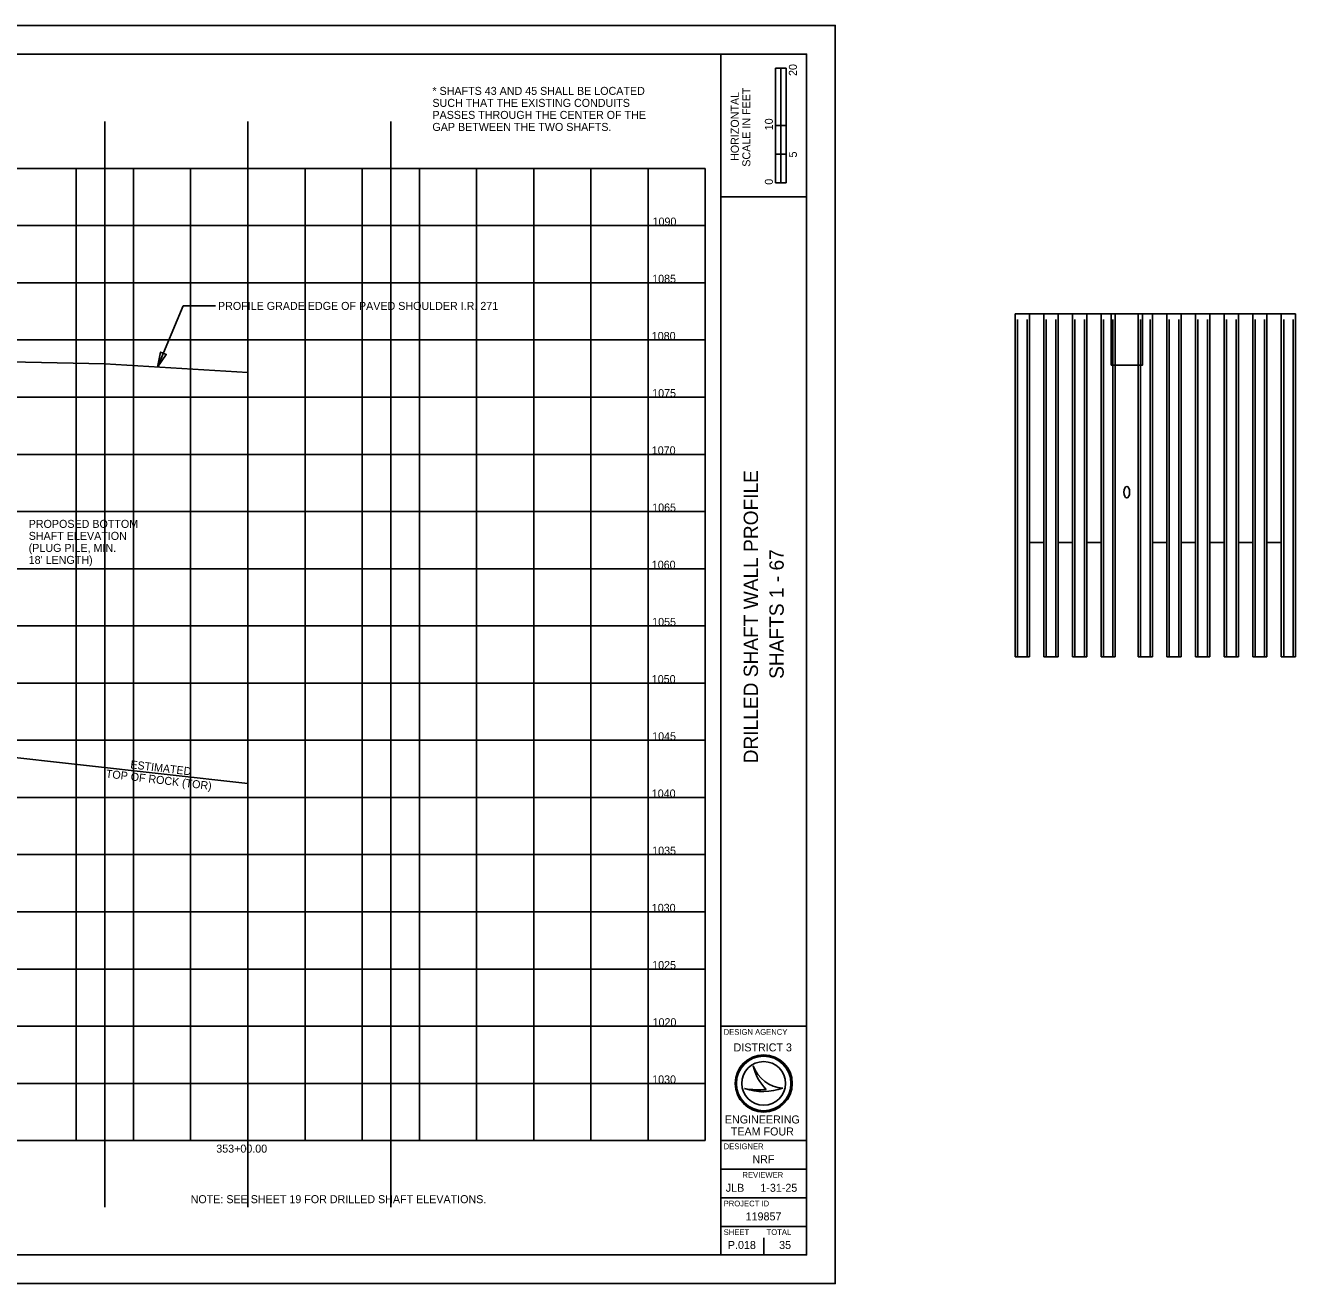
# Model space of a CAD drawing. Extents: x -190 to 421, y 1 to 366.
# Drawn here: x 199 to 421.1, y 0.6 to 220.6 of the extents above; entities that cross this region are included whole.
import ezdxf

# ---------------------------------------------------------------- set-up
doc = ezdxf.new("R2010")
doc.units = 0
for name, color, linetype in [('BR_P_Beam_Reinforcing', 7, 'Continuous'), ('DR_X_Culvert', 7, 'Continuous'), ('PF_P_Sta_Elev_Text', 7, 'Continuous'), ('RD_P_Wall', 7, 'Continuous'), ('RD_X_Bedrock', 7, 'Continuous'), ('SC_Scratch1', 7, 'Continuous'), ('SH_Border', 7, 'Continuous'), ('SH_Cut_Line', 7, 'Continuous'), ('SH_Data', 7, 'Continuous'), ('SH_Major_Grid_Line', 7, 'Continuous'), ('XS_X_Ground_Line', 7, 'Continuous')]:
    doc.layers.add(name, color=color, linetype=linetype)

msp = doc.modelspace()

# ---------------------------------------------------------------- linework, layer by layer
at = {"layer": 'BR_P_Beam_Reinforcing'}
for p, q in [((372.51, 110.18), (372.51, 169.18)), ((374.18, 110.18), (374.18, 169.18)), ((377.51, 110.18), (377.51, 169.18)), ((379.18, 110.18), (379.18, 169.18)), ((382.51, 110.18), (382.51, 169.18)), ((384.18, 110.18), (384.18, 169.18)), ((387.51, 110.18), (387.51, 169.18)), ((389.18, 161.18), (389.18, 169.18)), ((394.01, 161.18), (394.01, 169.18)), ((395.68, 110.18), (395.68, 169.18)), ((399.01, 110.18), (399.01, 169.18)), ((400.68, 110.18), (400.68, 169.18)), ((404.03, 110.18), (404.03, 169.18)), ((405.7, 110.18), (405.7, 169.18)), ((409.03, 110.18), (409.03, 169.18)), ((410.7, 110.18), (410.7, 169.18)), ((414.03, 110.18), (414.03, 169.18)), ((415.7, 110.18), (415.7, 169.18)), ((419.03, 110.18), (419.03, 169.18)), ((420.7, 110.18), (420.7, 169.18)), ((389.18, 110.18), (389.18, 161.18)), ((394.01, 110.18), (394.01, 161.18))]:
    msp.add_line(p, q, dxfattribs=at)
at = {"layer": 'DR_X_Culvert'}
msp.add_ellipse((391.59, 138.98), major_axis=(0, 1), ratio=0.5, dxfattribs=at)
at = {"layer": 'RD_P_Wall'}
for p, q in [((372.09, 170.18), (372.09, 110.18)), ((372.09, 170.18), (374.59, 170.18)), ((374.59, 170.18), (374.59, 130.18)), ((374.59, 170.18), (374.59, 110.18)), ((377.09, 170.18), (377.09, 110.18)), ((377.09, 170.18), (379.59, 170.18)), ((379.59, 170.18), (379.59, 110.18)), ((379.59, 170.18), (379.59, 130.18)), ((382.09, 170.18), (382.09, 110.18)), ((382.09, 170.18), (384.59, 170.18)), ((384.59, 170.18), (384.59, 110.18)), ((384.59, 170.18), (384.59, 130.18)), ((387.09, 170.18), (387.09, 110.18)), ((387.09, 170.18), (389.59, 170.18)), ((389.59, 161.18), (389.59, 170.18)), ((393.59, 170.18), (396.09, 170.18)), ((393.59, 161.18), (393.59, 170.18)), ((396.09, 170.18), (396.09, 110.18)), ((396.09, 170.18), (396.09, 130.18)), ((398.59, 170.18), (398.59, 110.18)), ((398.59, 170.18), (401.09, 170.18)), ((401.09, 170.18), (401.09, 110.18)), ((401.09, 170.18), (401.09, 130.18)), ((403.61, 170.18), (403.61, 110.18)), ((403.61, 170.18), (406.11, 170.18)), ((406.11, 170.18), (406.11, 110.18)), ((406.11, 170.18), (406.11, 130.18)), ((408.61, 170.18), (408.61, 110.18)), ((408.61, 170.18), (411.11, 170.18)), ((411.11, 170.18), (411.11, 110.18)), ((411.11, 170.18), (411.11, 130.18)), ((413.61, 170.18), (413.61, 110.18)), ((413.61, 170.18), (416.11, 170.18)), ((416.11, 170.18), (416.11, 110.18)), ((416.11, 170.18), (416.11, 130.18)), ((418.61, 170.18), (418.61, 110.18)), ((418.61, 170.18), (421.11, 170.18)), ((421.11, 170.18), (421.11, 110.18)), ((389.59, 161.18), (389.59, 110.18)), ((393.59, 161.18), (393.59, 110.18)), ((372.09, 110.18), (374.59, 110.18)), ((377.09, 110.18), (379.59, 110.18)), ((382.09, 110.18), (384.59, 110.18)), ((387.09, 110.18), (389.59, 110.18)), ((393.59, 110.18), (396.09, 110.18)), ((398.59, 110.18), (401.09, 110.18)), ((403.61, 110.18), (406.11, 110.18)), ((408.61, 110.18), (411.11, 110.18)), ((413.61, 110.18), (416.11, 110.18)), ((418.61, 110.18), (421.11, 110.18))]:
    msp.add_line(p, q, dxfattribs=at)
for points in [[(374.59, 170.18), (377.09, 170.18), (377.09, 130.18), (374.59, 130.18)], [(379.59, 170.18), (382.09, 170.18), (382.09, 130.18), (379.59, 130.18)], [(384.59, 170.18), (387.09, 170.18), (387.09, 130.18), (384.59, 130.18)], [(396.09, 170.18), (398.59, 170.18), (398.59, 130.18), (396.09, 130.18)], [(401.09, 170.18), (403.59, 170.18), (403.59, 130.18), (401.09, 130.18)], [(406.11, 170.18), (408.61, 170.18), (408.61, 130.18), (406.11, 130.18)], [(411.11, 170.18), (413.61, 170.18), (413.61, 130.18), (411.11, 130.18)], [(416.11, 170.18), (418.61, 170.18), (418.61, 130.18), (416.11, 130.18)]]:
    msp.add_lwpolyline(points, dxfattribs=at)
msp.add_lwpolyline([(388.84, 161.18), (394.34, 161.18), (394.34, 170.18), (388.84, 170.18)], close=True, dxfattribs=at)
at = {"layer": 'RD_X_Bedrock'}
msp.add_line((37.89, 110.21), (237.89, 88.06), dxfattribs=at)
at = {"layer": 'SC_Scratch1'}
for p, q in [((212.89, 13.94), (212.89, 203.81)), ((237.89, 13.94), (237.89, 203.81)), ((262.89, 13.94), (262.89, 203.81))]:
    msp.add_line(p, q, dxfattribs=at)
at = {"layer": 'SH_Border'}
for p, q in [((320.6, 5.6), (320.6, 215.6)), ((320.6, 190.6), (335.6, 190.6)), ((320.6, 45.6), (335.6, 45.6)), ((320.6, 25.6), (335.6, 25.6)), ((320.6, 20.6), (335.6, 20.6)), ((320.6, 15.6), (335.6, 15.6)), ((320.6, 10.6), (335.6, 10.6))]:
    msp.add_line(p, q, dxfattribs=at)
msp.add_lwpolyline([(15.6, 215.6), (335.6, 215.6), (335.6, 5.6), (15.6, 5.6)], close=True, dxfattribs=at)
at = {"layer": 'SH_Cut_Line'}
msp.add_lwpolyline([(0.6, 0.6), (340.6, 0.6), (340.6, 220.6), (0.6, 220.6)], close=True, dxfattribs=at)
at = {"layer": 'SH_Data'}
for p, q in [((330.17, 193.1), (330.17, 213.1)), ((332.04, 213.1), (330.17, 213.1)), ((330.17, 203.1), (330.17, 213.1)), ((330.17, 213.1), (331.1, 213.1)), ((331.1, 213.1), (331.11, 213.1)), ((331.11, 213.1), (331.11, 203.1)), ((332.04, 213.1), (332.04, 193.1)), ((331.11, 203.1), (330.17, 203.1)), ((332.03, 203.1), (331.1, 203.1)), ((331.1, 203.1), (331.1, 198.1)), ((332.03, 198.1), (332.03, 203.1)), ((331.1, 198.1), (330.17, 198.1)), ((330.17, 198.1), (330.17, 193.1)), ((331.1, 193.1), (331.1, 198.1)), ((331.1, 198.1), (332.03, 198.1)), ((17.89, 195.6), (317.89, 195.6)), ((317.89, 25.6), (317.89, 195.6)), ((332.04, 193.1), (330.17, 193.1)), ((330.17, 193.1), (331.1, 193.1)), ((232.21, 171.58), (226.61, 171.58)), ((326.27, 38.7), (326.27, 38.7)), ((328.1, 35.6), (328.1, 35.6)), ((324.77, 34.7), (324.77, 34.7)), ((331.47, 34.79), (331.47, 34.79)), ((17.89, 25.6), (317.89, 25.6)), ((324.35, 7.35), (324.35, 7.35)), ((328.1, 5.6), (328.1, 8.6))]:
    msp.add_line(p, q, dxfattribs=at)
msp.add_lwpolyline([(222.11, 160.87), (226.61, 171.58)], dxfattribs=at)
msp.add_lwpolyline([(222.11, 160.87), (222.64, 163.49), (223.61, 163.08)], close=True, dxfattribs=at)
for radius in [5, 4.77, 4.77, 3.82]:
    msp.add_circle((328.1, 35.6), radius, dxfattribs=at)
for centre, radius, start, end in [((331.76, 40.58), 5.8, 198.9257, 198.9319), ((334.07, 40.3), 7.96, 191.6379, 191.6421), ((331.76, 40.58), 5.8, 198.9319, 267.1657), ((334.07, 40.3), 7.96, 191.6421, 226.0947), ((327.99, 44.3), 10.13, 251.4576, 290.0832), ((327.08, 47.14), 12.66, 259.4964, 259.4995), ((327.99, 44.3), 10.13, 251.4527, 251.4576), ((327.08, 47.14), 12.66, 259.4995, 276.6672)]:
    msp.add_arc(centre, radius, start, end, dxfattribs=at)
at = {"layer": 'SH_Major_Grid_Line'}
for p, q in [((207.89, 25.6), (207.89, 195.6)), ((217.89, 25.6), (217.89, 195.6)), ((227.89, 25.6), (227.89, 195.6)), ((237.89, 25.6), (237.89, 195.6)), ((247.89, 25.6), (247.89, 195.6)), ((257.89, 25.6), (257.89, 195.6)), ((267.89, 25.6), (267.89, 195.6)), ((277.89, 25.6), (277.89, 195.6)), ((287.89, 25.6), (287.89, 195.6)), ((297.89, 25.6), (297.89, 195.6)), ((307.89, 25.6), (307.89, 195.6)), ((17.89, 185.6), (317.89, 185.6)), ((17.89, 175.6), (317.89, 175.6)), ((17.89, 165.6), (317.89, 165.6)), ((17.89, 155.6), (317.89, 155.6)), ((317.89, 25.6), (317.89, 155.6)), ((17.89, 145.6), (317.89, 145.6)), ((17.89, 135.6), (317.89, 135.6)), ((17.89, 125.6), (317.89, 125.6)), ((17.89, 115.6), (317.89, 115.6)), ((17.89, 105.6), (317.89, 105.6)), ((17.89, 95.6), (317.89, 95.6)), ((17.89, 85.6), (317.89, 85.6)), ((17.89, 75.6), (317.89, 75.6)), ((17.89, 65.6), (317.89, 65.6)), ((17.89, 55.6), (317.89, 55.6)), ((17.89, 45.6), (317.89, 45.6)), ((17.89, 35.6), (317.89, 35.6))]:
    msp.add_line(p, q, dxfattribs=at)
at = {"layer": 'XS_X_Ground_Line'}
msp.add_lwpolyline([(37.89, 171.36), (62.89, 169.76), (87.89, 168.12), (112.89, 166.52), (162.89, 163.4), (187.89, 161.92), (212.89, 161.42), (237.89, 159.92)], dxfattribs=at)

# ---------------------------------------------------------------- texts
at = {"layer": 'PF_P_Sta_Elev_Text'}
for s, p in [('1090', (308.67, 185.6)), ('1085', (308.6, 175.6)), ('1080', (308.53, 165.6)), ('1075', (308.6, 155.6)), ('1070', (308.53, 145.6)), ('1065', (308.6, 135.6)), ('1060', (308.53, 125.6)), ('1055', (308.6, 115.6)), ('1050', (308.53, 105.6)), ('1045', (308.6, 95.6)), ('1040', (308.53, 85.6)), ('1035', (308.6, 75.6)), ('1030', (308.53, 65.6)), ('1025', (308.6, 55.6)), ('1020', (308.67, 45.6)), ('1030', (308.6, 35.6)), ('353+00.00', (232.37, 23.5))]:
    msp.add_text(s, height=1.4, dxfattribs=at).set_placement(p)
at = {"layer": 'SH_Data'}
for s, height, rotation, p in [('20', 1.4, 90, (333.9, 211.76)), ('HORIZONTAL', 1.4, 90, (323.75, 196.9)), ('SCALE IN FEET', 1.4, 90, (325.77, 195.89)), ('10', 1.4, 90, (329.7, 202.26)), ('5', 1.4, 90, (333.9, 197.5)), ('0', 1.4, 90, (329.7, 192.74)), ('DRILLED SHAFT WALL PROFILE', 2.5, 90, (327.1, 91.57)), ('SHAFTS 1 - 67', 2.5, 90, (331.6, 106.34)), ('ESTIMATED ', 1.4, 353.2227, (217.29, 90.71)), ('TOP OF ROCK (TOR)', 1.4, 353.2227, (213, 89.1))]:
    msp.add_text(s, height=height, rotation=rotation, dxfattribs=at).set_placement(p)
for s, height, p in [('* SHAFTS 43 AND 45 SHALL BE LOCATED', 1.4, (270.17, 208.45)), ('SUCH THAT THE EXISTING CONDUITS ', 1.4, (270.17, 206.35)), ('PASSES THROUGH THE CENTER OF THE', 1.4, (270.17, 204.25)), ('GAP BETWEEN THE TWO SHAFTS.', 1.4, (270.17, 202.15)), ('PROFILE GRADE EDGE OF PAVED SHOULDER I.R. 271', 1.4, (232.67, 170.85)), ('PROPOSED BOTTOM', 1.4, (199.57, 132.74)), ('SHAFT ELEVATION', 1.4, (199.57, 130.64)), ('(PLUG PILE, MIN.', 1.4, (199.57, 128.54)), ("18' LENGTH)", 1.4, (199.57, 126.44)), ('DESIGN AGENCY', 1, (321.1, 44.1)), ('DISTRICT 3', 1.4, (322.84, 41.2)), ('ENGINEERING', 1.4, (321.31, 28.6)), ('TEAM FOUR', 1.4, (322.35, 26.5)), ('DESIGNER', 1, (321.1, 24.1)), ('NRF', 1.4, (326.13, 21.65)), ('REVIEWER', 1, (324.38, 19.1)), ('JLB', 1.4, (321.47, 16.65)), ('1-31-25', 1.4, (327.52, 16.65)), ('NOTE: SEE SHEET 19 FOR DRILLED SHAFT ELEVATIONS.', 1.4, (227.89, 14.66)), ('PROJECT ID', 1, (321.1, 14.1)), ('119857', 1.4, (324.95, 11.65)), ('SHEET', 1, (321.1, 9.1)), ('TOTAL', 1, (328.6, 9.1)), ('P.018', 1.4, (321.84, 6.65)), ('35', 1.4, (330.8, 6.65))]:
    msp.add_text(s, height=height, dxfattribs=at).set_placement(p)

doc.saveas('drawing.dxf')
